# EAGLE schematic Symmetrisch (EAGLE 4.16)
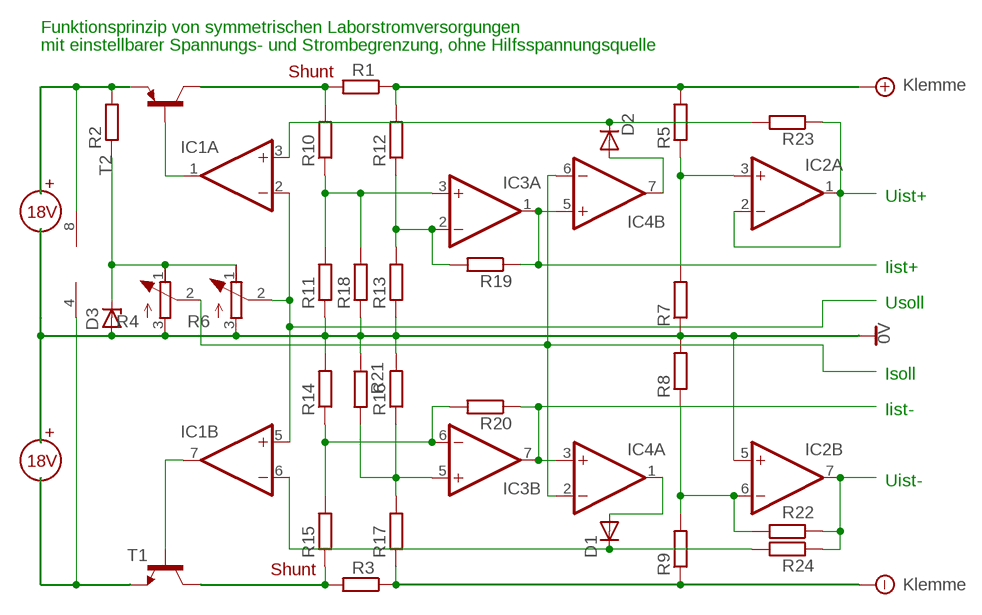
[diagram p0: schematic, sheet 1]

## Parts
D1  DIODE-D-10  [D-10]
D2  DIODE-D-10  [D-10]
D3  ZENER-DIODEF126-10  [F126Z10]
IC1  TL082P  [DIL08]
IC2  TL082P  [DIL08]
IC3  TL082P  [DIL08]
IC4  TL082P  [DIL08]
R1  R-EU_0207/10  [0207/10]
R2  R-EU_0207/10  [0207/10]
R3  R-EU_0207/10  [0207/10]
R4  R-TRIMMT93YB  [RTRIMT93YB]
R5  R-EU_0207/10  [0207/10]
R6  R-TRIMMT93YB  [RTRIMT93YB]
R7  R-EU_0207/10  [0207/10]
R8  R-EU_0207/10  [0207/10]
R9  R-EU_0207/10  [0207/10]
R10  R-EU_0207/10  [0207/10]
R11  R-EU_0207/10  [0207/10]
R12  R-EU_0207/10  [0207/10]
R13  R-EU_0207/10  [0207/10]
R14  R-EU_0207/10  [0207/10]
R15  R-EU_0207/10  [0207/10]
R16  R-EU_0207/10  [0207/10]
R17  R-EU_0207/10  [0207/10]
R18  R-EU_0207/10  [0207/10]
R19  R-EU_0207/10  [0207/10]
R20  R-EU_0207/10  [0207/10]
R21  R-EU_0207/10  [0207/10]
R22  R-EU_0207/10  [0207/10]
R23  R-EU_0207/10  [0207/10]
R24  R-EU_0207/10  [0207/10]
T1  -NPN-TO3/  [TO3]
T2  -PNP-TO220  [TO220]

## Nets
0V: D3.A IC2.5(B:+IN) R4.3(E) R6.3(E) R7.1 R8.2 R11.1 R13.1 R14.2 R16.2 R18.1 R21.1
+12V: R1.1 R5.2 R12.2 ; supply symbol labelled Klemme
+UB: IC1.8(P:V+) R2.2 T2.3(E)
-UB: IC1.4(P:V-) R3.1 R9.1 R17.1 T1.E ; supply symbol labelled Klemme
N$2: R1.2 R10.2 T2.2(C)
N$3: IC1.1(A:OUT) T2.1(B)
N$4: D3.C R2.1 R4.1(A) R6.1(A)
N$5: IC1.7(B:OUT) T1.B
N$6: R3.2 R15.1 T1.C
N$7: IC2.3(A:+IN) R5.1 R7.2
N$8: IC2.6(B:-IN) R8.1 R9.2 R22.2
N$9: IC1.2(A:-IN) IC1.5(B:+IN) R6.2(S)
N$10: IC3.3(A:+IN) R10.1 R11.2 R18.2
N$11: IC2.1(A:OUT) IC2.2(A:-IN) R23.1
N$12: IC3.5(B:+IN) R16.1 R17.2 R21.2
N$13: IC3.2(A:-IN) R12.1 R13.2 R19.2
N$14: IC3.1(A:OUT) IC4.5(B:+IN) R19.1
N$15: IC3.7(B:OUT) IC4.3(A:+IN) R20.1
N$16: IC3.6(B:-IN) R14.1 R15.2 R20.2
N$17: IC4.2(A:-IN) IC4.6(B:-IN) R4.2(S)
N$18: IC2.7(B:OUT) R22.1 R24.1
N$19: D1.C IC1.6(B:-IN) R24.2
N$20: D2.C IC1.3(A:+IN) R23.2
N$21: D2.A IC4.7(B:OUT)
N$22: D1.A IC4.1(A:OUT)

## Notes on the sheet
- Funktionsprinzip von symmetrischen Laborstromversorgungen
- mit einstellbarer Spannungs- und Strombegrenzung, ohne Hilfsspannungsquelle
- Shunt
- +
- Uist+
- 18V
- Iist+
- Usoll
- Isoll
- Iist-
- +
- 18V
- Uist-
- Shunt

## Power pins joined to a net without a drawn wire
V+: IC2.8(P:V+) IC3.8(P:V+) IC4.8(P:V+)
V-: IC2.4(P:V-) IC3.4(P:V-) IC4.4(P:V-)

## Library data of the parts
D1 D2 = diode:DIODE-: DIODE
D3 = diode:ZENER-DIODE: Z-Diode
IC1-IC4 = linear:TL082: OP AMP
R1-R3 R5 R7-R24 = rcl:R-EU_: RESISTOR, European symbol
R4 R6 = rcl:R-TRIMM: Trimm resistor
T1 = transistor:*-NPN-: NPN Transistror
T2 = transistor:*-PNP-: PNP Transistror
